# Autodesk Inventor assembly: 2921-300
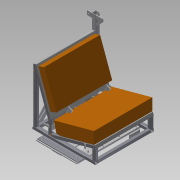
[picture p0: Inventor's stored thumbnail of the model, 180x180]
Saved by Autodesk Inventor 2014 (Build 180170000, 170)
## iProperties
Company: NHTSA/VRTC
Created: 2012-02
Part Number: 2921-300
Document SubType Name: Assembly
Designer: Mike Vanvoorhis
Project: CHILD SIDE IMPACT SLED
Description: BENCH ASSEMBLY
Mass: 100140 g
Surface Area: 63627.5 cm^2
Volume: 13304.9 cm^3
Density: 7.52656 g/cm^3
DESIGN DATE: 2012-11-05
Author: Dave Walker
Title: Bench Assembly
Subject: Child Side Impact Sled
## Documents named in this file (19)
- B:\VRTC_DWG\BIO\Non-P572\Child Side-Frontal Impact Sled\Side Impact Sled\Bench_Assembly.iam
- B:\VRTC_DWG\BIO\Non-P572\Child Side-Frontal Impact Sled\Side Impact Sled\Bench_Frame_Assembly.iam
- B:\VRTC_DWG\BIO\Non-P572\Child Side-Frontal Impact Sled\Side Impact Sled\Washer 0.50.ipt
- B:\VRTC_DWG\BIO\Non-P572\Child Side-Frontal Impact Sled\Side Impact Sled\Nut Hex 0.5-13.ipt
- B:\VRTC_DWG\BIO\Non-P572\Child Side-Frontal Impact Sled\Side Impact Sled\Bench_Seat_Panel.ipt
- B:\VRTC_DWG\BIO\Non-P572\Child Side-Frontal Impact Sled\Side Impact Sled\Washer 0.25.ipt
- B:\VRTC_DWG\BIO\Non-P572\Child Side-Frontal Impact Sled\Side Impact Sled\Bench_Seat_Back_Panel.ipt
- B:\VRTC_DWG\BIO\Non-P572\Child Side-Frontal Impact Sled\Side Impact Sled\Lower Anchor_Assembly.iam
- B:\VRTC_DWG\BIO\Non-P572\Child Side-Frontal Impact Sled\Side Impact Sled\Bottom_Seat_Cushion_Assembly.iam
- B:\VRTC_DWG\BIO\Non-P572\Child Side-Frontal Impact Sled\Side Impact Sled\Seat_Back_Cushion_Assembly.iam
- B:\VRTC_DWG\Inventor Support Files\Content Center\en-US\ANSI B18.2.2(09)\ANSI B18.2.2 - 1_4 - 28(2).ipt
- B:\VRTC_DWG\BIO\Non-P572\Child Side-Frontal Impact Sled\Side Impact Sled\Rail Bearing Mount Plate Assembly.iam
- B:\VRTC_DWG\Inventor Support Files\Content Center\en-US\ANSI B18.22.1\ANSI B18.22.1 - 3_8 - wide - Type A.ipt
- B:\VRTC_DWG\Inventor Support Files\Content Center\en-US\ANSI B18.3(05)\ANSI B18.3 - 3_8-16 UNC - 0.75(31).ipt
- B:\VRTC_DWG\Inventor Support Files\Content Center\en-US\ANSI B18.3(03)\ANSI B18.3 - 1_4-20 UNC - UNC - 0.375(1).ipt
- B:\VRTC_DWG\Inventor Support Files\Content Center\en-US\ANSI B18.3(05)\ANSI B18.3 - 1_2-13 UNC - 1.5(31).ipt
- B:\VRTC_DWG\BIO\Non-P572\Child Side-Frontal Impact Sled\Side Impact Sled\Top Tether Anchor.ipt
- B:\VRTC_DWG\Inventor Support Files\Content Center\en-US\ANSI B18.2.2(09)\ANSI B18.2.2 - 1_4 - 20(2).ipt
- B:\VRTC_DWG\Inventor Support Files\Content Center\en-US\ANSI ASME B18.2.1(2)\ANSI_ASME B18.2.1 - 1_4-20 UNC - 2(2).ipt
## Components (96 placed, 18 different names)
1. Bench_Frame_Assembly:1 [sub-assembly] — Insert:49, Insert:50, Insert:51, Insert:52, Mate:1, Flush:1, Mate:2, Mate:4, Mate:5, Insert:207, Mate:23, Insert:208, Insert:209, Insert:210, Mate:24, Insert:211, Mate:25, Mate:27, Mate:29, Insert:212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
2. Bench_Seat_Panel:1 — Mate:1, Flush:2, Mate:2, Insert:169, Insert:170, Insert:171, Insert:172, Insert:173, Insert:174, Insert:175, Insert:176, Insert:177, Insert:178, Insert:179, Insert:180, Insert:181, Insert:182, Insert:183, Insert:184
3. Bench_Seat_Back_Panel:1 — Insert:73, Insert:75, Insert:76, Insert:77, Insert:78, Insert:80, Mate:3, Mate:4, Mate:5, Mate:6, Angle:1, Mate:7, Insert:191, Insert:192, Insert:193, Insert:194, Insert:195, Insert:196
4. Rail Bearing Mount Plate Assembly:1 [sub-assembly] — Insert:208, Insert:209, Mate:26, Mate:28, Mate:30, Mate:32, Mate:34, Mate:36
5. Lower_Anchor_Assembly:1 [sub-assembly] — Insert:207, Mate:23
6. Bottom_Seat_Cushion_Assembly:1 [sub-assembly] — Insert:177, Insert:178
7. Seat_Back_Cushion_Assembly:1 [sub-assembly] — Mate:6, Angle:1, Mate:7
8. Top Tether Anchor:1 — Insert:224, Angle:2, Insert:225
9. Hex Bolt - Inch 1/4-20 UNC - 2:1 — Insert:225
10. Hex Nut - Inch 1/4 - 20:1 — Insert:227
11. Washer 0.25:29 — Insert:226, Insert:227
12. Hexagon Socket Head Cap Screw - Inch 1/2 - 13 UNC - 1 1/2:1
13. Hexagon Socket Head Cap Screw - Inch 1/2 - 13 UNC - 1 1/2:2
14. Hexagon Socket Head Cap Screw - Inch 1/2 - 13 UNC - 1 1/2:3
15. Hexagon Socket Head Cap Screw - Inch 1/2 - 13 UNC - 1 1/2:4
16. Washer 0.50:1 — Insert:49, Insert:56
17. Washer 0.50:2 — Insert:50, Insert:55
18. Washer 0.50:3 — Insert:51, Insert:53
19. Washer 0.50:4 — Insert:52, Insert:54
20. Nut Hex 0.5-13:1 — Insert:54
21. Nut Hex 0.5-13:2 — Insert:53
22. Nut Hex 0.5-13:3 — Insert:55
23. Nut Hex 0.5-13:4 — Insert:56
24. Washer 0.25:1 — Insert:175
25. Washer 0.25:2 — Insert:174
26. Washer 0.25:3 — Insert:173
27. Washer 0.25:4 — Insert:171
28. Washer 0.25:5 — Insert:170
29. Washer 0.25:6 — Insert:169
30. Washer 0.25:7 — Insert:172
31. Washer 0.25:8 — Insert:176
32. Hexagon Socket Button Head Cap Screw - Inch 1/4 - 20 x 3/8:1
33. Hexagon Socket Button Head Cap Screw - Inch 1/4 - 20 x 3/8:2
34. Hexagon Socket Button Head Cap Screw - Inch 1/4 - 20 x 3/8:3
35. Hexagon Socket Button Head Cap Screw - Inch 1/4 - 20 x 3/8:4
36. Hexagon Socket Button Head Cap Screw - Inch 1/4 - 20 x 3/8:5
37. Hexagon Socket Button Head Cap Screw - Inch 1/4 - 20 x 3/8:6
38. Hexagon Socket Button Head Cap Screw - Inch 1/4 - 20 x 3/8:7
39. Hexagon Socket Button Head Cap Screw - Inch 1/4 - 20 x 3/8:8
40. Washer 0.25:9 — Insert:76
41. Washer 0.25:10 — Insert:75
42. Washer 0.25:12 — Insert:73
43. Washer 0.25:13 — Insert:77
44. Washer 0.25:14 — Insert:78
45. Washer 0.25:16 — Insert:80
46. Hexagon Socket Button Head Cap Screw - Inch 1/4 - 20 x 3/8:9
47. Hexagon Socket Button Head Cap Screw - Inch 1/4 - 20 x 3/8:10
48. Hexagon Socket Button Head Cap Screw - Inch 1/4 - 20 x 3/8:11
49. Hexagon Socket Button Head Cap Screw - Inch 1/4 - 20 x 3/8:12
50. Hexagon Socket Button Head Cap Screw - Inch 1/4 - 20 x 3/8:13
51. Hexagon Socket Button Head Cap Screw - Inch 1/4 - 20 x 3/8:14
52. Plain Washer (Inch) 3/8 - wide - Type A:1 — Insert:210, Insert:214
53. Plain Washer (Inch) 3/8 - wide - Type A:2 — Mate:24
54. Plain Washer (Inch) 3/8 - wide - Type A:3 — Mate:25, Mate:26, Insert:216
55. Plain Washer (Inch) 3/8 - wide - Type A:4 — Mate:27, Mate:28, Insert:217
56. Plain Washer (Inch) 3/8 - wide - Type A:5 — Mate:29, Mate:30, Insert:218
57. Plain Washer (Inch) 3/8 - wide - Type A:6 — Insert:211, Insert:215
58. Plain Washer (Inch) 3/8 - wide - Type A:7 — Insert:212, Insert:223
59. Plain Washer (Inch) 3/8 - wide - Type A:8 — Mate:31, Mate:32, Insert:220
60. Plain Washer (Inch) 3/8 - wide - Type A:9 — Mate:33, Mate:34, Insert:221
61. Plain Washer (Inch) 3/8 - wide - Type A:10 — Mate:35, Mate:36, Insert:222
62. Plain Washer (Inch) 3/8 - wide - Type A:11 — Insert:213, Insert:219
63. Hexagon Socket Head Cap Screw - Inch 3/8 - 16 UNC - 3/4:1 — Insert:214
64. Hexagon Socket Head Cap Screw - Inch 3/8 - 16 UNC - 3/4:2 — Insert:215
65. Hexagon Socket Head Cap Screw - Inch 3/8 - 16 UNC - 3/4:3 — Insert:216
66. Hexagon Socket Head Cap Screw - Inch 3/8 - 16 UNC - 3/4:4 — Insert:217
67. Hexagon Socket Head Cap Screw - Inch 3/8 - 16 UNC - 3/4:5 — Insert:218
68. Hexagon Socket Head Cap Screw - Inch 3/8 - 16 UNC - 3/4:6 — Insert:219
69. Hexagon Socket Head Cap Screw - Inch 3/8 - 16 UNC - 3/4:10 — Insert:223
70. Hexagon Socket Head Cap Screw - Inch 3/8 - 16 UNC - 3/4:7 — Insert:220
71. Hexagon Socket Head Cap Screw - Inch 3/8 - 16 UNC - 3/4:8 — Insert:221
72. Hexagon Socket Head Cap Screw - Inch 3/8 - 16 UNC - 3/4:9 — Insert:222
73. Washer 0.25:17 — Insert:183, Insert:189
74. Washer 0.25:18 — Insert:182, Insert:190
75. Washer 0.25:19 — Insert:181, Insert:188
76. Washer 0.25:20 — Insert:180, Insert:187
77. Washer 0.25:21 — Insert:179, Insert:186
78. Washer 0.25:22 — Insert:184, Insert:185
79. Hex Nut - Inch 1/4 - 28:1 — Insert:185
80. Hex Nut - Inch 1/4 - 28:2 — Insert:186
81. Hex Nut - Inch 1/4 - 28:3 — Insert:187
82. Hex Nut - Inch 1/4 - 28:4 — Insert:188
83. Hex Nut - Inch 1/4 - 28:5 — Insert:189
84. Hex Nut - Inch 1/4 - 28:6 — Insert:190
85. Washer 0.25:23 — Insert:192, Insert:200
86. Washer 0.25:24 — Insert:193, Insert:201
87. Washer 0.25:25 — Insert:194, Insert:202
88. Washer 0.25:26 — Insert:196, Insert:198
89. Washer 0.25:27 — Insert:195, Insert:197
90. Washer 0.25:28 — Insert:191, Insert:199
91. Hex Nut - Inch 1/4 - 28:7 — Insert:198
92. Hex Nut - Inch 1/4 - 28:8 — Insert:200
93. Hex Nut - Inch 1/4 - 28:9 — Insert:201
94. Hex Nut - Inch 1/4 - 28:10 — Insert:202
95. Hex Nut - Inch 1/4 - 28:11 — Insert:199
96. Hex Nut - Inch 1/4 - 28:12 — Insert:197
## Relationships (94: Insert 69, Mate 21, Flush 2, Angle 2)
- Insert:49: Bench_Frame_Assembly:1 ↔ Washer 0.50:1
- Insert:50: Bench_Frame_Assembly:1 ↔ Washer 0.50:2
- Insert:51: Bench_Frame_Assembly:1 ↔ Washer 0.50:3
- Insert:52: Bench_Frame_Assembly:1 ↔ Washer 0.50:4
- Insert:53: Washer 0.50:3 ↔ Nut Hex 0.5-13:2
- Insert:54: Washer 0.50:4 ↔ Nut Hex 0.5-13:1
- Insert:55: Washer 0.50:2 ↔ Nut Hex 0.5-13:3
- Insert:56: Washer 0.50:1 ↔ Nut Hex 0.5-13:4
- Insert:73: Bench_Seat_Back_Panel:1 ↔ Washer 0.25:12
- Insert:75: Bench_Seat_Back_Panel:1 ↔ Washer 0.25:10
- Insert:76: Bench_Seat_Back_Panel:1 ↔ Washer 0.25:9
- Insert:77: Bench_Seat_Back_Panel:1 ↔ Washer 0.25:13
- Insert:78: Bench_Seat_Back_Panel:1 ↔ Washer 0.25:14
- Insert:80: Bench_Seat_Back_Panel:1 ↔ Washer 0.25:16
- Mate:1: Bench_Frame_Assembly:1 ↔ Bench_Seat_Panel:1
- Flush:1: Bench_Frame_Assembly:1
- Flush:2: Bench_Seat_Panel:1
- Mate:2: Bench_Frame_Assembly:1 ↔ Bench_Seat_Panel:1
- Insert:169: Bench_Seat_Panel:1 ↔ Washer 0.25:6
- Insert:170: Bench_Seat_Panel:1 ↔ Washer 0.25:5
- Insert:171: Bench_Seat_Panel:1 ↔ Washer 0.25:4
- Insert:172: Bench_Seat_Panel:1 ↔ Washer 0.25:7
- Insert:173: Bench_Seat_Panel:1 ↔ Washer 0.25:3
- Insert:174: Bench_Seat_Panel:1 ↔ Washer 0.25:2
- Insert:175: Bench_Seat_Panel:1 ↔ Washer 0.25:1
- Insert:176: Bench_Seat_Panel:1 ↔ Washer 0.25:8
- Mate:3: Bench_Seat_Back_Panel:1
- Mate:4: Bench_Frame_Assembly:1 ↔ Bench_Seat_Back_Panel:1
- Mate:5: Bench_Frame_Assembly:1 ↔ Bench_Seat_Back_Panel:1
- Insert:177: Bench_Seat_Panel:1 ↔ Bottom_Seat_Cushion_Assembly:1
- Insert:178: Bench_Seat_Panel:1 ↔ Bottom_Seat_Cushion_Assembly:1
- Insert:179: Bench_Seat_Panel:1 ↔ Washer 0.25:21
- Insert:180: Bench_Seat_Panel:1 ↔ Washer 0.25:20
- Insert:181: Bench_Seat_Panel:1 ↔ Washer 0.25:19
- Insert:182: Bench_Seat_Panel:1 ↔ Washer 0.25:18
- Insert:183: Bench_Seat_Panel:1 ↔ Washer 0.25:17
- Insert:184: Bench_Seat_Panel:1 ↔ Washer 0.25:22
- Insert:185: Washer 0.25:22 ↔ Hex Nut - Inch 1/4 - 28:1
- Insert:186: Washer 0.25:21 ↔ Hex Nut - Inch 1/4 - 28:2
- Insert:187: Washer 0.25:20 ↔ Hex Nut - Inch 1/4 - 28:3
- Insert:188: Washer 0.25:19 ↔ Hex Nut - Inch 1/4 - 28:4
- Insert:189: Washer 0.25:17 ↔ Hex Nut - Inch 1/4 - 28:5
- Insert:190: Washer 0.25:18 ↔ Hex Nut - Inch 1/4 - 28:6
- Mate:6: Bench_Seat_Back_Panel:1 ↔ Seat_Back_Cushion_Assembly:1
- Angle:1: Bench_Seat_Back_Panel:1 ↔ Seat_Back_Cushion_Assembly:1
- Mate:7: Bench_Seat_Back_Panel:1 ↔ Seat_Back_Cushion_Assembly:1
- Insert:191: Bench_Seat_Back_Panel:1 ↔ Washer 0.25:28
- Insert:192: Bench_Seat_Back_Panel:1 ↔ Washer 0.25:23
- Insert:193: Bench_Seat_Back_Panel:1 ↔ Washer 0.25:24
- Insert:194: Bench_Seat_Back_Panel:1 ↔ Washer 0.25:25
- Insert:195: Bench_Seat_Back_Panel:1 ↔ Washer 0.25:27
- Insert:196: Bench_Seat_Back_Panel:1 ↔ Washer 0.25:26
- Insert:197: Washer 0.25:27 ↔ Hex Nut - Inch 1/4 - 28:12
- Insert:198: Washer 0.25:26 ↔ Hex Nut - Inch 1/4 - 28:7
- Insert:199: Washer 0.25:28 ↔ Hex Nut - Inch 1/4 - 28:11
- Insert:200: Washer 0.25:23 ↔ Hex Nut - Inch 1/4 - 28:8
- Insert:201: Washer 0.25:24 ↔ Hex Nut - Inch 1/4 - 28:9
- Insert:202: Washer 0.25:25 ↔ Hex Nut - Inch 1/4 - 28:10
- Insert:207: Bench_Frame_Assembly:1 ↔ Lower_Anchor_Assembly:1
- Mate:23: Bench_Frame_Assembly:1 ↔ Lower_Anchor_Assembly:1
- Insert:208: Bench_Frame_Assembly:1 ↔ Rail Bearing Mount Plate Assembly:1
- Insert:209: Bench_Frame_Assembly:1 ↔ Rail Bearing Mount Plate Assembly:1
- Insert:210: Bench_Frame_Assembly:1 ↔ Plain Washer (Inch) 3/8 - wide - Type A:1
- Mate:24: Bench_Frame_Assembly:1 ↔ Plain Washer (Inch) 3/8 - wide - Type A:2
- Insert:211: Bench_Frame_Assembly:1 ↔ Plain Washer (Inch) 3/8 - wide - Type A:6
- Mate:25: Bench_Frame_Assembly:1 ↔ Plain Washer (Inch) 3/8 - wide - Type A:3
- Mate:26: Rail Bearing Mount Plate Assembly:1 ↔ Plain Washer (Inch) 3/8 - wide - Type A:3
- Mate:27: Bench_Frame_Assembly:1 ↔ Plain Washer (Inch) 3/8 - wide - Type A:4
- Mate:28: Rail Bearing Mount Plate Assembly:1 ↔ Plain Washer (Inch) 3/8 - wide - Type A:4
- Mate:29: Bench_Frame_Assembly:1 ↔ Plain Washer (Inch) 3/8 - wide - Type A:5
- Mate:30: Rail Bearing Mount Plate Assembly:1 ↔ Plain Washer (Inch) 3/8 - wide - Type A:5
- Insert:212: Bench_Frame_Assembly:1 ↔ Plain Washer (Inch) 3/8 - wide - Type A:7
- Mate:31: Bench_Frame_Assembly:1 ↔ Plain Washer (Inch) 3/8 - wide - Type A:8
- Mate:32: Rail Bearing Mount Plate Assembly:1 ↔ Plain Washer (Inch) 3/8 - wide - Type A:8
- Mate:33: Bench_Frame_Assembly:1 ↔ Plain Washer (Inch) 3/8 - wide - Type A:9
- Mate:34: Rail Bearing Mount Plate Assembly:1 ↔ Plain Washer (Inch) 3/8 - wide - Type A:9
- Mate:35: Bench_Frame_Assembly:1 ↔ Plain Washer (Inch) 3/8 - wide - Type A:10
- Mate:36: Rail Bearing Mount Plate Assembly:1 ↔ Plain Washer (Inch) 3/8 - wide - Type A:10
- Insert:213: Bench_Frame_Assembly:1 ↔ Plain Washer (Inch) 3/8 - wide - Type A:11
- Insert:214: Plain Washer (Inch) 3/8 - wide - Type A:1 ↔ Hexagon Socket Head Cap Screw - Inch 3/8 - 16 UNC - 3/4:1
- Insert:215: Plain Washer (Inch) 3/8 - wide - Type A:6 ↔ Hexagon Socket Head Cap Screw - Inch 3/8 - 16 UNC - 3/4:2
- Insert:216: Plain Washer (Inch) 3/8 - wide - Type A:3 ↔ Hexagon Socket Head Cap Screw - Inch 3/8 - 16 UNC - 3/4:3
- Insert:217: Plain Washer (Inch) 3/8 - wide - Type A:4 ↔ Hexagon Socket Head Cap Screw - Inch 3/8 - 16 UNC - 3/4:4
- Insert:218: Plain Washer (Inch) 3/8 - wide - Type A:5 ↔ Hexagon Socket Head Cap Screw - Inch 3/8 - 16 UNC - 3/4:5
- Insert:219: Plain Washer (Inch) 3/8 - wide - Type A:11 ↔ Hexagon Socket Head Cap Screw - Inch 3/8 - 16 UNC - 3/4:6
- Insert:220: Plain Washer (Inch) 3/8 - wide - Type A:8 ↔ Hexagon Socket Head Cap Screw - Inch 3/8 - 16 UNC - 3/4:7
- Insert:221: Plain Washer (Inch) 3/8 - wide - Type A:9 ↔ Hexagon Socket Head Cap Screw - Inch 3/8 - 16 UNC - 3/4:8
- Insert:222: Plain Washer (Inch) 3/8 - wide - Type A:10 ↔ Hexagon Socket Head Cap Screw - Inch 3/8 - 16 UNC - 3/4:9
- Insert:223: Plain Washer (Inch) 3/8 - wide - Type A:7 ↔ Hexagon Socket Head Cap Screw - Inch 3/8 - 16 UNC - 3/4:10
- Insert:224: Bench_Frame_Assembly:1 ↔ Top Tether Anchor:1
- Angle:2: Bench_Frame_Assembly:1 ↔ Top Tether Anchor:1
- Insert:225: Top Tether Anchor:1 ↔ Hex Bolt - Inch 1/4-20 UNC - 2:1
- Insert:226: Bench_Frame_Assembly:1 ↔ Washer 0.25:29
- Insert:227: Hex Nut - Inch 1/4 - 20:1 ↔ Washer 0.25:29
